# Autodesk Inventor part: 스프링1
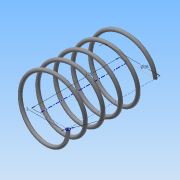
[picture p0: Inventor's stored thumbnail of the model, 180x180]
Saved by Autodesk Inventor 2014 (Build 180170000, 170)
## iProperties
Created: 2015-06
Part Number: 스프링1
Material: 강철, 연강
Document SubType Name: Modeling
Designer: MYHOME
Density: 7.86 g/cm^3
Appearance: 강철
Mass: 1.52988 g
Surface Area: 7.87024 cm^2
Volume: 0.194641 cm^3
Author: MYHOME
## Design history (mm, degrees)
sketch "스케치1"
  geometry: L1 (0, 0)-(8, 0); L2 (8, 0)-(8, 14.5); L3 (8, 14.5)-(0, 14.5); L4 (0, 14.5)-(0, 0); C1 r 0.5 at (8, 0)
  constraints: 8 end point, 2 parallel, 1 centre point, 1 coincident, 1 horizontal, 1 perpendicular
  dimensions: "d0" = 1 diameter of C1; "d1" = 16 diameter of L2 L4; "d2" = 14.5 distance of L3.end L1.start (derived)
feature "코일1" pitch "d3" = 10; turns "d5" = 5; dims "d4" = 14.5 (= d2), "d6" = 0, angle "d7" = 90 deg, angle "d8" = 90 deg, "d9" = 0, "d10" = 0
sketch "스케치2"
  geometry: L1 (-8.5, 0)-(-7.5, 0) reference; 1 further point
  constraints: 1 horizontal alignment
extrude "돌출1" cut sketch "스케치2" distance "d11" = 10; taper "d12" = 0 deg
node "작업 평면1"
sketch "스케치3"
  geometry: L1 (-7.5, 0)-(-8.5, 0) reference; 1 further point
  constraints: 1 horizontal alignment
extrude "돌출2" cut sketch "스케치3" distance "d14" = 10; taper "d15" = 0 deg
node "솔리드1"
node "절단 모서리 투영1"
node "절단 모서리 투영2"
other parameters: "d13" = 14.5 (= d2)
